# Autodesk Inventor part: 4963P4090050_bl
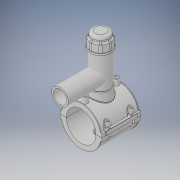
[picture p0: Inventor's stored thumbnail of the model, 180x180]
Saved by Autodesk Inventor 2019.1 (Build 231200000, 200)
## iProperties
Created: 2017-07
Part Number: 4963P4090050_bl
Material: Generic
Document SubType Name: Modeling
Designer: KIM
Density: 1 g/cm^3
Appearance: Default
Author: KIM
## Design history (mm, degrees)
derived "4963P4.ipt"
feature "Solid1::4963P4.ipt" dims "ScaleForDerivedMember" = 10
feature "Solid2::4963P4.ipt" dims "ScaleForDerivedMember" = 10
feature "Solid3::4963P4.ipt" dims "ScaleForDerivedMember" = 10
tag "TaggingFeature1"
body "Solid1"
body "Solid2"
body "Solid3"
other parameters: "d2" = 126 [user parameter], "d3" = 22.5 [user parameter], "d4" = 118 [user parameter], "d5" = 0 [user parameter], "d6" = 0.1 [user parameter], "d8" = 0 [user parameter], "d19" = 6 [user parameter], "d20" = 6 [user parameter], "d21" = 70.8 [user parameter], "d23" = 0 [user parameter], "d24" = 35.4 [user parameter], "d26" = 0 [user parameter], "d27" = 3 [user parameter], "d28" = 3 [user parameter], "d29" = 3 [user parameter], "d31" = 6 [user parameter], "d32" = 0 [user parameter], "d33" = 0 [user parameter], "d34" = 0.6 [user parameter], "d40" = 60.84 [user parameter], "d41" = 63 [user parameter], "d43" = 0 [user parameter], "d45" = 0 [user parameter], "d47" = 129.3 [user parameter], "d70" = 15 [user parameter], "d72" = 0 [user parameter], "d73" = 6 [user parameter], "d75" = 5 [user parameter], "d76" = 0 [user parameter], "d77" = 4.5 [user parameter], "d78" = 75 [user parameter], "d79" = 15 [user parameter], "d80" = 47.2 [user parameter], "d82" = 5 deg [user parameter], "d84" = 4 [user parameter], "d85" = 14 [user parameter], "d86" = 0 [user parameter], "d87" = 3 [user parameter], "d88" = 0 [user parameter], "d89" = 1 [user parameter], "d90" = 1 [user parameter], "d91" = 94.4 [user parameter], "d92" = 0 [user parameter], "d93" = 0.5 [user parameter], "d94" = 47.36842 [user parameter], "d96" = 119.34 [user parameter], "d97" = 2.36 [user parameter], "d98" = 0 [user parameter], "d102" = 0.9 [user parameter], "d120" = 140 deg [user parameter], "d121" = 24.228 [user parameter], "d122" = 20 deg [user parameter], "d123" = 234 [user parameter], "d124" = 70.2 [user parameter], "d126" = 0 [user parameter], "d143" = 92.7 [user parameter], "d145" = 20.76923 [user parameter], "d149" = 1.35 [user parameter], "d150" = 22.84615 [user parameter], "d153" = 118 [user parameter], "d154" = 0 [user parameter], "d156" = 58.5 [user parameter], "d157" = 160 deg [user parameter], "d159" = 5.4 [user parameter], "d161" = 1.35 [user parameter], "d162" = 70.8 [user parameter], "d163" = 0 [user parameter], "d164" = 45 [user parameter], "d167" = 9 [user parameter], "d168" = 57.07317 [user parameter], "d170" = 3.75 [user parameter], "d172" = 0 [user parameter], "d173" = 1 [user parameter], "d175" = 45 [user parameter], "d176" = 20 deg [user parameter], "d177" = 6.3 [user parameter], "d178" = 27 [user parameter], "d180" = 0 [user parameter], "d183" = 10.8 [user parameter], "d184" = 5.04 [user parameter], "d185" = 38.35 [user parameter], "d186" = 38.35 [user parameter], "d187" = 58.5 [user parameter], "d188" = 8.1 [user parameter], "d189" = 6.3 [user parameter], "d190" = 0 [user parameter], "d191" = 87.75 [user parameter], "d193" = 8 [user parameter], "d194" = 4.13 [user parameter], "d195" = 90 deg [user parameter], "d197" = 0 [user parameter], "d199" = 0 [user parameter], "d200" = 13.5 [user parameter], "d202" = 0 [user parameter], "d203" = 177 [user parameter], "d204" = 59.85 [user parameter], "d205" = 44.1 [user parameter], "d206" = 53.55 [user parameter], "d207" = 132.75 [user parameter], "d208" = 138.06 [user parameter], "d209" = 164.61 [user parameter], "d210" = 54.18 [user parameter], "d211" = 63 [user parameter], "d212" = 50.4 [user parameter], "d213" = 35.1 [user parameter], "d216" = 0 [user parameter], "d217" = 9 [user parameter], "d218" = 9 [user parameter], "d219" = 1.8 [user parameter], "d224" = 0 [user parameter], "d225" = 64 [user parameter], "d228" = 123 [user parameter], "d230" = 5.4 [user parameter], "B_" = 126 [user parameter], "L_" = 118 [user parameter], "d_t" = 6 [user parameter], "H_2" = 177 [user parameter], "H_1" = 64 [user parameter], "H_" = 123 [user parameter], "d1" = 117 [user parameter]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
